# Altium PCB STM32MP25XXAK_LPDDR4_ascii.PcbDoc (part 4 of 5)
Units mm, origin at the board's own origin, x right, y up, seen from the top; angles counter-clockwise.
Board outline 120 x 79.6 mm, 4 copper layers (Top Layer, Signal Layer 1, Signal Layer 2, Bottom Layer), stack 1.614 mm thick; 190 components, 143 nets, 1208 pads, 757 vias.
Unrouted connection lines stored in the file: 3.
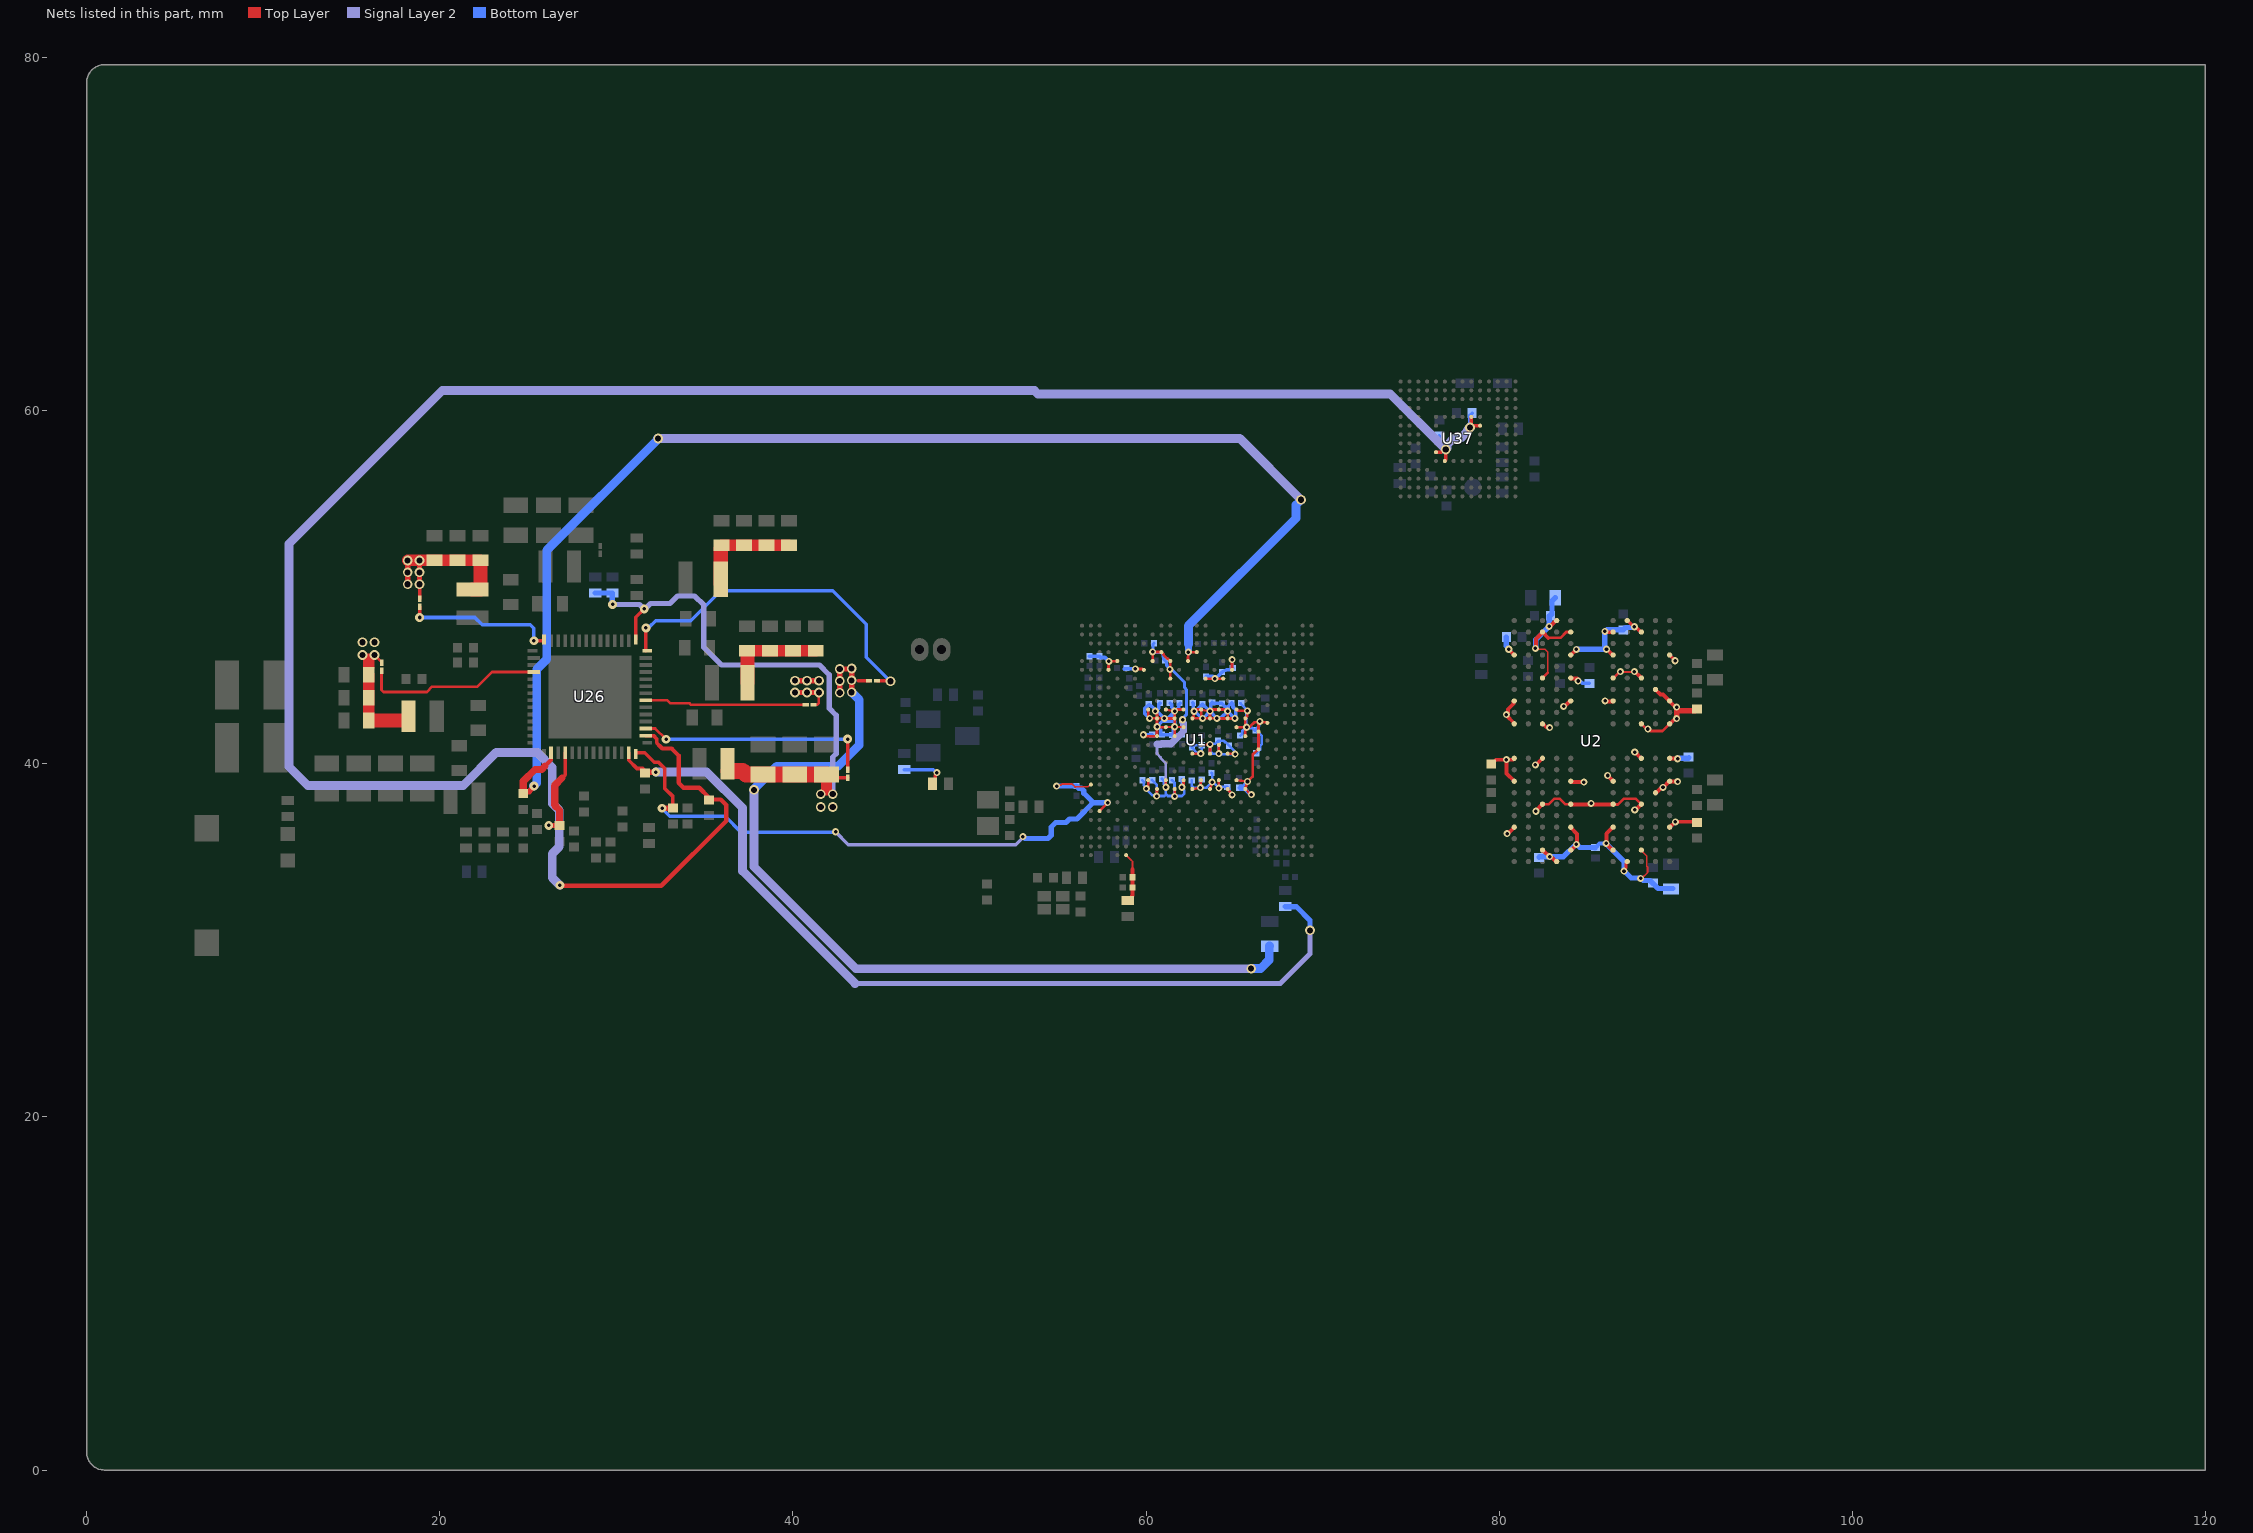
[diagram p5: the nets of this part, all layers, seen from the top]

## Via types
v1: diameter 0.55, hole 0.35, Top Layer to Bottom Layer, 277 vias
v2: diameter 0.4, hole 0.2, Top Layer to Bottom Layer, tented both sides, 229 vias
v3: diameter 0.5, hole 0.2, Top Layer to Bottom Layer, 146 vias
v4: diameter 0.4, hole 0.2, Top Layer to Bottom Layer, 105 vias

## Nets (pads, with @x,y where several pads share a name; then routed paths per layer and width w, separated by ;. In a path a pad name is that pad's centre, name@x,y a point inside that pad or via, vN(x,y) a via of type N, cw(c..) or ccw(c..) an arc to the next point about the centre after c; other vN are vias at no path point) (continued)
VDD2_DDR: C10.2 C11.2 C12.1 C13.1 C14.1 C15.1 C16.1 C17.1 C18.1 C19.1 C20.1 C21.1 C41.2 C75.2 C76.2 C77.1 C82.2 C83.2 C200.2 C202.2 L5.2 LNK8.2 R2.2 U1.1C11 U1.1D12 U1.1E11 U1.1F12 U1.1L11 U1.1M12 U1.M22 U1.N21 U1.R21 U2.A4 U2.A9 U2.AA3 U2.AA5 U2.AA8 U2.AA10 U2.AB4 U2.AB9 U2.B3 U2.B5 U2.B8 U2.B10 U2.D1 U2.D5 U2.D8 U2.D12 U2.F3 U2.F5 U2.F8 U2.F10 U2.G2 U2.H1 U2.H5 U2.H8 U2.H12 U2.K1 U2.K3 U2.K10 U2.K12 U2.N1 U2.N3 U2.N10 U2.N12 U2.R1 U2.R5 U2.R8 U2.R12 U2.T2 U2.U3 U2.U5 U2.U8 U2.U10 U2.W1 U2.W5 U2.W8 U2.W12 | length 84
  Top Layer w0.09: v4@82.121,46.482 82.614,46.482 82.754,46.341 82.754,45.159 ; U2.U5@86.46,44.865 U2.U5@86.48,44.865 ; v4@86.844,45.229 v4(86.865,45.229) 86.89,45.204 87.64,45.204 v4(87.665,45.229) ; U2.AB4@87.26,48.115 U2.AB4@87.285,48.115 ; v4@87.635,47.765 v4(87.659,47.765) ; v4(88.016,33.516) 88.083,33.516 88.405,33.838 88.405,34.168 88.369,34.204 88.369,34.784 U2.B3@88.059,35.094 ; U2.K1@89.659,40.369 U2.K1@89.684,40.369
  Top Layer w0.1: U2.W8@84.06,46.165 U2.W8@84.06,46.167 ; v4@84.38,46.487 v4(84.38,46.49) ; U2.W1@89.66,46.158 U2.W1@89.66,46.165 ; v4(89.972,45.84) v4@89.972,45.846
  Top Layer w0.15: v1(16.298,46.165) 16.7,45.763 LNK8.2@16.7,45.723 ; U1.1L11@65.125,39.075 v2(65.75,39) U1.1M12@65.625,38.575 65.625,38.565 65.9,38.29 65.94,38.29 v2(65.97,38.26) ; U1.1E11@65.125,42.075 65.625,42.075 cw(c65.663,41.93) v2(65.7,42.075) ; U1.1C11@65.125,43.075 65.147,43.075 65.222,43 65.735,43 65.731,42.996 65.731,42.703 65.625,42.597 U1.1D12@65.625,42.575 65.625,42.15 v2(65.7,42.075) ; U1.1F12@65.625,41.575 65.625,42 v2(65.7,42.075) ; v2@65.736,42.111 65.89,42.111 66.137,42.357 v2@66.407,42.357 ; U2.F10@82.459,37.694 82.469,37.704 82.803,37.704 83.129,38.03 83.389,38.03 ; U2.U10@82.46,44.865 82.754,45.159 ; 82.785,47.138 83.478,47.138 83.805,47.465 U2.AA8@84.06,47.465 ; 83.39,38.029 83.43,38.029 83.741,37.719 U2.F8@84.059,37.719 ; U2.F5@86.459,37.694 86.734,37.694 87.072,38.032 87.721,38.032 U2.F3@88.034,37.719 ; U2.U5@86.48,44.865 v4@86.844,45.229
  Top Layer w0.16: v2(65.75,39) 66.042,39.292 66.042,40.512 U1.R21@66.32,40.79 ; U1.R21@66.321,40.79 U1.R21@66.363,40.832 ; U1.R21@66.375,40.825 66.363,40.837 66.363,41.813 U1.N21@66.375,41.825 66.375,42.325 v2(66.45,42.4) 66.493,42.357 66.843,42.357 U1.M22@66.875,42.325 ; v4(87.076,33.92) 87.076,33.985 87.193,34.102 87.193,34.105 87.196,34.108 87.196,34.363 87.26,34.427 U2.A4@87.26,34.465 ; U2.N3@88.06,42.265 88.35,41.975 v4(88.425,41.975) 88.546,41.854 89.249,41.854 U2.N1@89.66,42.265
  Top Layer w0.2: v4@80.546,46.484 v4(80.546,46.49) ; U2.W12@80.86,46.165 U2.W12@80.86,46.171 ; v4(82.835,47.79) 82.873,47.828 v4@82.946,47.828 ; U2.AB9@83.233,48.115 U2.AB9@83.26,48.115 ; v4(85.99,47.505) 86.03,47.465 U2.AA5@86.46,47.465 ; U2.AB4@87.285,48.115 v4@87.635,47.765 ; v4(87.659,47.765) 87.697,47.727 87.771,47.727 88.033,47.465 U2.AA3@88.06,47.465 ; U2.W1@89.66,46.158 v4@89.972,45.846
  Top Layer w0.22: C13.1@79.559,39.979 79.814,40.235 v4(80.415,40.235) ; v4@80.488,36.045 80.51,36.045 U2.D12@80.859,36.394 ; v4@80.546,46.484 U2.W12@80.86,46.171 ; U2.H12@80.859,39.021 80.421,39.459 80.421,40.229 v4(80.415,40.235) ; U2.K12@80.859,40.294 80.856,40.297 U2.K12@80.842,40.297 ; U2.K12@80.86,40.315 U2.K12@80.842,40.297 ; U2.N12@80.86,42.265 80.86,42.301 80.414,42.747 v4(80.414,42.784) 80.414,42.832 80.504,42.922 80.504,42.924 80.51,42.93 80.51,43.093 80.82,43.403 80.82,43.503 80.86,43.543 U2.R12@80.86,43.565 ; v4@82.059,39.919 82.072,39.919 82.447,40.294 U2.K10@82.459,40.294 ; v4@82.086,37.344 82.436,37.694 U2.F10@82.459,37.694 ; v4@82.089,46.574 82.089,47.074 82.459,47.444 82.479,47.444 82.785,47.138 ; U2.B10@82.459,35.094 82.462,35.097 82.493,35.097 82.845,34.744 v4(82.86,34.744) ; U2.N10@82.459,42.244 82.491,42.244 82.497,42.25 82.672,42.074 82.826,42.074 v4@82.86,42.04 ; v4@82.859,34.719 82.893,34.685 82.997,34.685 83.237,34.444 U2.A9@83.259,34.444 ; v4@82.946,47.828 U2.AB9@83.233,48.115 ; v4(83.66,43.253) 83.704,43.253 84.016,43.565 U2.R8@84.06,43.565 ; U2.B8@84.059,35.094 v4@84.384,35.419 ; U2.D8@84.059,36.394 84.419,36.034 v4@84.419,35.503 ; U2.F8@84.059,37.719 84.072,37.707 85.122,37.707 85.134,37.719 85.147,37.707 86.447,37.707 U2.F5@86.459,37.694 ; U2.H8@84.059,39.015 84.081,39.015 84.131,38.965 v4(84.809,38.965) ; U2.U8@84.059,44.844 84.074,44.829 84.426,44.829 84.46,44.794 v4@84.509,44.794 ; U2.W8@84.06,46.167 v4@84.38,46.487 ; v4(86.01,43.565) 86.042,43.532 U2.R5@86.422,43.532 ; v4(86.085,46.49) 86.11,46.49 86.435,46.165 U2.W5@86.46,46.165 ; v4(86.145,39.34) U2.H5@86.46,39.025 ; U2.B5@86.459,35.094 86.059,35.494 86.089,35.524 86.089,36.044 U2.D5@86.46,36.415 ; v4@87.679,45.243 88.032,44.891 88.032,44.883 U2.U3@88.059,44.856 ; v4(87.685,37.39) 87.733,37.39 87.817,37.474 88.037,37.694 U2.F3@88.059,37.694 ; v4(87.685,40.665) 87.697,40.665 88.046,40.316 U2.K3@88.059,40.316 ; U2.T2@88.832,44.199 88.854,44.199 89.134,43.919 89.284,43.919 89.95,43.253 90.025,43.253 v4@90.059,43.219 ; U2.G2@88.859,38.344 88.881,38.344 v4@89.171,38.635 ; v4(89.285,38.665) 89.298,38.665 89.628,38.995 89.658,38.995 89.659,38.994 v4@90.109,38.994 ; U2.D1@89.659,36.394 89.984,36.719 C15.1@91.159,36.719 ; U2.K1@89.659,40.307 89.659,40.294 v4@90.109,40.294 ; U2.N1@89.659,42.244 89.95,42.535 90.025,42.535 v4@90.059,42.569 ; v4(80.415,40.235) 80.78,40.235 U2.K12@80.842,40.297
  Top Layer w0.3: v4@90.059,42.569 v4@90.059,43.219 ; 90.259,43.014 91.079,43.014 C14.1@91.184,43.119
  Top Layer w0.64: C202.2@15.975,42.45 C41.2@15.975,43.75 C200.2@15.975,45.05 ; 15.975,45.495 15.975,45.925
  Top Layer w0.8: C202.2@16.2,42.45 L5.2@17.975,42.45
  Bottom Layer w0.15: C83.2@65.35,43.425 v2@65.627,43.148 ; C82.2@65.352,41.603 65.452,41.703 65.452,41.862 v2@65.625,42.035 ; v2@65.625,42.075 65.625,42.143 65.675,42.193 v2@65.675,42.99 ; v2@65.673,42.027 66.023,42.027 66.183,41.867 C75.2@66.218,41.867 ; C75.2@66.205,41.9 66.305,41.8 66.331,41.8 66.431,41.7 66.452,41.7 66.555,41.597 66.555,41.109 66.474,41.028 66.474,40.824 66.47,40.82
  Bottom Layer w0.16: C75.2@66.175,41.9 66.27,41.995 66.27,42.018 66.404,42.152 66.404,42.354 v2(66.45,42.4) ; C77.1@66.25,40.6 66.345,40.695 66.348,40.695 66.47,40.817 66.47,40.82
  Bottom Layer w0.2: v2(65.75,39) 65.476,38.726 65.466,38.726 65.463,38.723 65.349,38.723 C76.2@65.274,38.648 65.349,38.573 65.607,38.573 65.92,38.26 v2(65.97,38.26)
  Bottom Layer w0.22: v4@84.509,44.79 84.73,44.569 85.105,44.569 C21.1@85.109,44.565 ; R2.2@85.409,35.215 85.459,35.215 85.549,35.305 85.549,35.355 85.684,35.49 v4(86.06,35.49)
  Bottom Layer w0.3: C12.1@80.411,47.18 80.41,46.671 80.547,46.534 v4@80.547,46.485 ; v4@82.061,46.535 82.08,46.554 82.08,47.029 v4@82.836,47.785 ; C19.1@82.26,34.705 82.3,34.744 83.653,34.744 84.324,35.415 84.378,35.415 84.402,35.44 84.577,35.265 R2.2@85.461,35.265 ; v4(82.835,47.79) 82.834,48.365 C16.1@82.91,48.441 ; C16.1@82.911,48.39 82.996,48.475 82.996,49.225 C10.2@83.186,49.415 ; v4@84.381,46.485 86.086,46.485 86.086,46.534 85.991,46.629 85.991,47.499 86.04,47.499 86.13,47.59 C17.1@87.036,47.59 87.17,47.725 87.626,47.725 v4@87.66,47.76 ; v4(86.06,35.49) 87.077,34.473 87.077,33.915 87.104,33.915 87.489,33.531 87.998,33.531 88.017,33.511 88.088,33.455 88.162,33.397 88.553,33.397 88.58,33.345 C18.1@88.705,33.244 ; C18.1@88.604,33.345 C18.1@88.705,33.244 ; C18.1@88.71,33.24 C18.1@88.705,33.244 ; C11.2@89.834,32.94 89.009,32.94 C18.1@88.705,33.244 ; v4@90.109,40.29 90.143,40.324 90.718,40.324 C20.1@90.759,40.365
  other v1: 15.623,46.165 15.623,46.89 16.298,46.89
  other v2: 65.743,43
  other v4: 84.375,35.44 80.46,36.045 89.985,36.715 82.085,37.315 85.21,37.765 90.11,38.99 82.06,39.94 90.11,40.29 82.86,42.05 90.06,42.565 90.06,43.215 84.479,44.694 82.06,46.54
VDD3V3_USB: C61.2 R286.1 U26.13 | length 50.7
  Top Layer w0.21: U26.13@30.7,40.63 30.7,40.2 31.163,39.737 31.418,39.737 31.42,39.735 31.49,39.735 31.625,39.6 C61.2@31.625,39.53
  Top Layer w0.3: C61.2@31.625,39.53 v3(32.235,39.53)
  Signal Layer 2 w0.3: 43.518,27.562 67.603,27.562 69.284,29.244 v1(69.284,30.569)
  Signal Layer 2 w0.5: v3(32.235,39.53) 35.12,39.53 37.15,37.5 37.15,33.93 43.518,27.562
  Bottom Layer w0.3: R286.1@67.89,31.915 67.898,31.908 68.514,31.908 69.284,31.138 v1(69.284,30.569)
VDD_DDR_FB: LNK8.1 U26.46 | length 10.2
  Top Layer w0.15: LNK8.1@16.7,45.273 16.7,44.19 16.817,44.073 19.267,44.073 19.567,44.373 20.237,44.373 20.239,44.375 22.127,44.375 22.952,45.2 U26.46@25.33,45.2
VDD_EMMC: C9.2 C117.2 C190.1 U26.16 U37.E6 U37.F5 U37.J10 U37.K9 | length 132.2
  Top Layer w0.2: U37.E6@76.425,57.655 76.73,57.655 76.88,57.805 v1(76.975,57.805) 76.975,57.213 76.925,57.163 U37.F5@76.925,57.155 ; v1(78.35,59.055) v1@78.425,59.13 ; U37.J10@78.425,59.655 78.425,59.225 78.417,59.217 78.417,59.138 v1@78.425,59.13 ; U37.K9@78.925,59.155 78.545,59.155 78.512,59.122 78.433,59.122 v1@78.425,59.13
  Top Layer w0.21: U26.16@31.67,41.6 32.1,41.6 32.288,41.412 32.288,41.187 32.434,41.041
  Top Layer w0.25: v3@26.752,33.092 32.549,33.092 36.225,36.768 36.225,37.668 35.912,37.981 C190.1@35.266,37.981 ; 32.432,41.038 32.598,40.872 33.128,40.872 33.525,40.475 33.525,38.925 33.8,38.65 34.695,38.65 35.25,38.095 C190.1@35.25,38.025
  Signal Layer 2 w0.5: v3(26.8,33.125) 26.372,33.553 26.372,34.908 26.765,35.301 26.765,37.369 26.372,37.762 26.372,39.786 25.509,40.649 23.203,40.649 21.327,38.773 12.524,38.773 11.458,39.839 11.458,52.457 20.147,61.146 53.676,61.146 53.869,60.953 73.827,60.953 76.886,57.894 v1(76.975,57.805) 76.975,57.819 77.05,57.894 77.05,58.059 77.431,58.44 77.819,58.44 78.2,58.821 78.2,58.891 78.34,59.032 v1@78.34,59.045
  Bottom Layer w0.2: C9.2@76.615,58.58 76.615,58.074 76.884,57.805 v1(76.975,57.805) ; v1(78.35,59.055) 78.35,59.739 C117.2@78.475,59.864
VDD_SDCARD: C215.1 U26.4 | length 5.1
  Top Layer w0.21: 26.925,39.2 27.1,39.375 U26.4@27.1,40.63
  Top Layer w0.3: v3(26.165,36.51) C215.1@26.775,36.51
  Top Layer w0.4: C215.1@26.775,36.51 26.775,37.393 26.51,37.658 26.51,38.785 26.925,39.2
VDDA1V8_AON: C189.2 C234.2 U1.AB3 U1.W2 U26.14 | length 37.9
  Top Layer w0.09: 56.026,38.692 56.705,38.692 56.837,38.825 U1.W2@56.875,38.825 ; v2@57.825,37.775 v2(57.825,37.8)
  Top Layer w0.1: v2(54.932,38.744) 54.99,38.801 55.205,38.801 55.267,38.863 55.805,38.863 55.975,38.692 56.026,38.692
  Top Layer w0.15: U1.AB3@57.375,37.325 v2@57.825,37.775
  Top Layer w0.21: U26.14@31.1,40.63 31.61,40.63 32.148,40.092 32.387,40.092 32.745,39.734 32.745,38.602 33.2,38.147 C189.2@33.2,37.49
  Top Layer w0.3: v3(32.59,37.49) C189.2@33.2,37.49
  Signal Layer 2 w0.2: v2(42.415,36.154) 43.144,35.425 52.627,35.425 53.025,35.823 v2(53.025,35.875)
  Bottom Layer w0.2: v3@32.57,37.493 33.032,37.031 36.158,37.031 37.056,36.133 42.394,36.133 v2(42.415,36.154)
  Bottom Layer w0.3: v2(53.025,35.875) 53.052,35.875 53.152,35.775 53.829,35.775 53.836,35.769 54.451,35.769 54.627,35.944 54.627,36.412 54.891,36.675 55.461,36.675 55.662,36.877 56.088,36.877 57.012,37.8 ; v2(54.932,38.744) 54.936,38.748 C234.2@56.064,38.748 56.199,38.613 56.338,38.613 56.479,38.472 56.479,38.333 57.012,37.8 ; v2(57.825,37.8) 57.012,37.8
VDDCORE: C22.2 C23.2 C24.2 C44.1 C45.2 C46.2 C47.1 C48.2 C49.2 C50.2 C51.2 C183.2 C192.2 C197.2 C201.2 L2.2 LNK2.2 R11.1 U1.1C1 U1.1C3 U1.1C5 U1.1D2 U1.1D4 U1.1E3 U1.1E5 U1.1F2 U1.1F4 U1.E5 U1.F4 U1.F8 | length 78.4
  Top Layer w0.15: U1.F4@57.875,45.325 v2(57.9,45.8) U1.E5@58.375,45.825 ; v2(59.4,45.375) 59.803,45.375 59.853,45.325 U1.F8@59.875,45.325 ; v2(59.85,41.65) 59.904,41.65 59.981,41.573 U1.1F2@60.624,41.573 ; U1.1C1@60.125,43.075 60.125,42.724 60.206,42.643 v2@60.206,42.575 ; v2(60.21,42.575) U1.1D2@60.625,42.575 ; v2@60.545,42.99 60.545,42.922 60.625,42.842 U1.1D2@60.625,42.575 ; U1.1F2@60.625,41.65 v2(60.625,42.1) ; U1.1C3@61.125,43.075 v2(61.625,42.983) ; U1.1F4@61.625,41.575 v2(61.625,42.1) ; U1.1E5@62.125,42.075 v2(61.625,42.1) ; U1.1C5@62.125,43.075 61.771,43.075 61.679,42.983 v2(61.625,42.983) ; v2(60.625,42.1) U1.1D2@60.625,42.575 ; v2(60.625,42.1) 60.65,42.075 U1.1E3@61.125,42.075 v2(61.625,42.1) ; U1.1D2@60.625,42.575 61.017,42.572 61.622,42.572 U1.1D4@61.625,42.575 ; v2(61.625,42.1) U1.1D4@61.625,42.575 ; U1.1D4@61.625,42.575 v2@61.625,42.983
  Top Layer w0.2: C22.2@39.775,52.375 C22.2@39.823,52.423 ; 43.7,44.7 LNK2.2@44.316,44.7
  Top Layer w0.3: v1(42.656,44.024) v1(42.656,44.699) v1(42.656,45.374) 43.331,45.374 v1@43.331,44.024
  Top Layer w0.64: C183.2@35.95,52.375 C24.2@37.225,52.375 C23.2@38.5,52.375 C22.2@39.775,52.375
  Top Layer w0.8: L2.2@35.915,50.2 L2.2@35.915,50.45 C183.2@35.915,52.173
  Signal Layer 2 w0.5: v1(37.8,38.525) 37.798,38.523 37.798,34.168 43.576,28.39 v1@65.911,28.39 ; v1@65.911,28.391 65.947,28.391 v1(65.956,28.4)
  Bottom Layer w0.2: C192.2@56.8,46.1 C201.2@57.375,46.1 57.45,46.025 57.675,46.025 v2(57.9,45.8) ; C197.2@58.755,45.355 58.775,45.375 v2(59.4,45.375) ; v2(59.85,41.65) 60.346,41.65 C44.1@60.351,41.655 ; v2@60.206,42.575 59.942,42.839 59.942,43.153 60.059,43.27 60.098,43.27 60.173,43.345 60.198,43.32 60.235,43.32 60.285,43.27 60.328,43.27 60.507,43.091 60.507,43.028 60.545,42.99 v2@60.578,42.99 ; C51.2@60.814,43.438 60.788,43.438 60.725,43.375 60.725,43.137 v2@60.578,42.99 ; C46.2@60.84,41.657 C46.2@60.913,41.657 ; C46.2@60.915,41.655 C46.2@60.913,41.657 ; v2@61.135,42.572 61.017,42.572 61.017,42.591 60.719,42.89 60.699,42.89 60.599,42.99 v2@60.578,42.99 ; C49.2@61.377,43.437 61.452,43.362 61.452,43.201 61.625,43.028 v2(61.625,42.983) v2@61.616,42.961 ; C47.1@61.476,41.631 C47.1@61.502,41.657 ; C50.2@61.941,43.438 61.866,43.363 61.866,43.211 v2@61.616,42.961 ; C48.2@62.038,41.657 C47.1@61.502,41.657 ; C46.2@60.913,41.657 C47.1@61.502,41.657 ; C46.2@60.913,41.657 60.84,41.73 60.84,41.94 60.719,42.062 60.663,42.062 v2(60.625,42.1) 60.625,42.107 60.923,42.405 v2@61.06,42.405 ; v2@61.06,42.405 v2@61.227,42.572 ; v2@61.06,42.405 61.623,42.405 ; v2@61.227,42.572 v2@61.616,42.961 ; v2@61.227,42.572 61.455,42.572 ; 61.455,42.572 v2@61.616,42.961 ; 61.455,42.572 61.623,42.405 ; C47.1@61.502,41.657 61.551,41.706 61.551,41.972 61.625,42.046 v2(61.625,42.1) 61.623,42.102 61.623,42.405
  Bottom Layer w0.5: v1(37.8,38.525) 37.81,38.535 37.81,38.592 39.084,39.866 42.555,39.866 43.757,41.068 43.757,43.623 v1(43.326,44.054) ; v1(65.956,28.4) 66.485,28.4 66.983,28.898 66.983,29.658 R11.1@67,29.675
  other v1: 43.326,44.729 43.326,45.404
  other v2: 61.04,42.575 60.531,42.99
VDDCORE_FB: LNK2.1 U26.28 | length 20.6
  Top Layer w0.2: U26.28@31.67,46.4 v3(31.67,47.7) ; LNK2.1@44.766,44.7 v1@45.376,44.7
  Bottom Layer w0.2: v3@31.645,47.7 31.702,47.757 31.876,47.757 32.229,48.111 34.209,48.111 35.902,49.804 42.248,49.804 44.15,47.902 44.15,46.041 v1@45.508,44.683 ; v3@31.65,47.703 31.707,47.761 31.881,47.761 32.234,48.114
  other v1: 45.533,44.683
VDDCPU: C26.2 C27.2 C28.2 C62.1 C63.2 C64.2 C65.1 C66.2 C67.2 C68.2 C69.2 L3.2 LNK4.1 U1.1C7 U1.1C9 U1.1D6 U1.1D8 U1.1D10 U1.F18 U1.G15 U1.G17 | length 28.3
  Top Layer w0.15: v2@62.725,42.907 v2@62.725,42.975 ; v2@63.2,42.575 U1.1D6@62.625,42.575 62.625,42.597 62.696,42.668 62.696,42.956 v2(62.72,42.98) 62.788,42.98 62.883,43.075 U1.1C7@63.125,43.075 ; U1.G15@63.375,44.825 v2(63.9,44.825) U1.G17@64.375,44.825 ; U1.F18@64.875,45.325 v2(64.875,45.91) ; v2@65.017,42.572 64.628,42.572 U1.1D10@64.625,42.575 ; U1.1C7@63.125,43.075 63.125,42.728 63.21,42.643 v2(63.21,42.575) U1.1D8@63.625,42.575 ; U1.1C7@63.125,43.075 v2(63.625,42.983) ; U1.1D8@63.625,42.575 v2(63.625,42.983) ; U1.1D8@63.625,42.575 v2(64.017,42.572) 64.622,42.572 U1.1D10@64.625,42.575 ; v2(63.625,42.983) 63.693,42.983 63.784,43.075 U1.1C9@64.125,43.075 64.466,43.075 64.557,42.983 v2(64.625,42.983) U1.1D10@64.625,42.575
  Top Layer w0.2: LNK4.1@18.85,49.35 v1(18.85,50.173)
  Top Layer w0.3: v1(18.175,50.173) v1(18.175,50.848) v1(18.175,51.523) v1(18.85,51.523) v1(18.85,50.848) v1(18.85,50.173)
  Top Layer w0.64: v1(18.175,51.523) v1(18.175,51.523) C27.2@19.7,51.525 C28.2@21,51.525 C26.2@22.3,51.525
  Top Layer w0.8: L3.2@21.85,49.875 22.3,49.875 22.3,51.173
  Bottom Layer w0.15: v2(64.875,45.91) 64.895,45.89 C66.2@64.895,45.441
  Bottom Layer w0.2: C63.2@62.65,43.455 62.685,43.42 v2@62.685,43.015 ; C67.2@63.4,44.95 63.775,44.95 v2(63.9,44.825) 63.933,44.825 64.23,45.122 64.23,45.127 64.3,45.197 C69.2@64.305,45.197 ; v2(64.017,42.572) 64.055,42.61 64.252,42.61 v2(64.625,42.983) ; v2@64.017,42.583 v2@63.625,42.975 ; C69.2@64.305,45.202 64.579,45.324 64.778,45.324 64.886,45.432 64.91,45.423 C66.2@64.915,45.421 ; v2@63.625,42.975 v2(63.625,42.983) ; v2@63.625,42.975 63.625,42.963 63.237,42.575 63.169,42.575 62.764,42.98 v2(62.72,42.98) 62.758,43.018 62.843,43.018 C62.1@63.2,43.375 63.275,43.3 63.308,43.3 v2(63.625,42.983) ; v2(63.625,42.983) 63.625,43.038 63.675,43.088 63.675,43.4 C65.1@63.75,43.475 63.784,43.441 64.284,43.441 C68.2@64.3,43.425 64.587,43.138 64.587,43.022 v2(64.625,42.983) ; v2(64.625,42.983) 64.658,43.016 64.658,43.258 C64.2@64.85,43.45 64.925,43.375 64.925,43.22 65.086,43.059 65.086,42.672 65.04,42.626 v2(65.04,42.572) 65.036,42.572 v2(64.625,42.983)
VDDCPU_FB: LNK4.2 U26.42 | length 8.6
  Top Layer w0.2: v3(18.85,48.29) LNK4.2@18.85,48.9 ; v3(25.325,46.975) U26.42@25.895,46.975
  Bottom Layer w0.2: v3(18.85,48.29) 21.979,48.29 22.394,47.875 25.123,47.875 25.325,47.673 v3(25.325,46.975)
VDDGPU: C34.2 C35.2 C36.2 C37.2 C52.2 C53.2 C54.2 C55.2 C57.2 C58.2 C59.2 C60.2 L4.2 LNK7.2 U1.1G7 U1.1G9 U1.1H6 U1.1H8 U1.1H10 U1.1L7 U1.1L9 U1.1M6 U1.1M8 U1.1M10 | length 24.7
  Top Layer w0.1: U1.1H6@62.625,40.575 U1.1H6@62.625,40.61
  Top Layer w0.125: v2(64.125,40.575) U1.1G9@64.125,41.075
  Top Layer w0.15: LNK7.2@41.175,43.35 41.182,43.358 41.385,43.358 41.473,43.445 v1(41.473,44.038) ; U1.1M6@62.625,38.575 v2(63.075,38.65) U1.1L7@63.125,39.075 ; U1.1H6@62.625,40.575 v2(63.1,40.575) ; U1.1G7@63.125,41.075 v2(63.625,41.1) U1.1H8@63.625,40.575 ; U1.1M8@63.625,38.575 v2(63.747,38.971) ; v2(64.125,38.629) U1.1L9@64.125,39.075 ; U1.1M10@64.625,38.575 v2(64.876,38.245)
  Top Layer w0.16: U1.1H10@64.625,40.575 v2(65.05,40.55)
  Top Layer w0.2: C35.2@41.55,46.393 C35.2@41.598,46.345
  Top Layer w0.3: v1(40.123,44.038) v1(40.798,44.038) v1(41.473,44.038) ; v1(40.123,44.713) v1(40.798,44.713) v1(41.473,44.713)
  Top Layer w0.64: C37.2@37.4,46.4 C36.2@38.7,46.4 C34.2@40,46.4 C35.2@41.3,46.4
  Top Layer w0.8: L4.2@37.425,44.6 37.425,46.073
  Bottom Layer w0.15: C57.2@62.592,39.053 62.592,38.738 62.68,38.65 v2(63.075,38.65) ; C60.2@63.154,39.122 63.092,39.06 63.092,38.667 v2(63.075,38.65) ; C59.2@63.714,39.486 63.747,39.453 v2(63.747,38.971) ; v2(64.876,38.245) 64.876,38.289 64.707,38.458 64.707,38.597 C58.2@64.607,38.697 64.193,38.697 v2(64.125,38.629) 63.783,38.971 v2(63.747,38.971) ; v2(63.075,38.65) 63.426,38.65 v2(63.747,38.971) ; C52.2@63.162,41.057 62.788,41.057 62.756,41.025 62.7,41.025 C55.2@62.6,40.925 62.902,40.623 63.052,40.623 v2(63.1,40.575) 63.162,40.637 C52.2@63.162,41.057 ; C52.2@63.162,41.057 63.184,41.079 63.603,41.079 v2(63.625,41.1) ; v2(63.625,41.1) 63.656,41.131 63.908,41.131 C53.2@64.083,41.306 ; v2(63.625,41.1) 63.625,40.719 63.769,40.575 v2(64.125,40.575) ; C53.2@64.083,41.306 64.396,41.306 64.463,41.239 64.496,41.239 C54.2@64.706,41.029 65.002,40.733 65.002,40.598 v2(65.05,40.55) 64.15,40.55 v2(64.125,40.575) ; C53.2@64.083,41.306 64.083,40.962 64.125,40.919 v2(64.125,40.575)
VDDGPU_FB: LNK7.1 U26.21 | length 9.3
  Top Layer w0.15: U26.21@31.55,43.6 32.883,43.6 33.06,43.423 34.14,43.423 34.213,43.35 LNK7.1@40.725,43.35
VDDIO: C70.1 C71.2 C72.2 C73.1 C74.2 C185.2 C186.2 C187.2 C196.2 C205.2 L6.2 LNK11.2 R27.2 R67.2 R260.2 R261.2 U1.1L1 U1.1L3 U1.1L5 U1.1M2 U1.1M4 U1.D10 U1.E9 U1.E11 U1.G11 U26.29 | length 59.1
  Top Layer w0.15: v2(60.025,38.6) 60.025,38.618 60.125,38.718 U1.1L1@60.125,39.075 ; U1.E9@60.375,45.825 U1.E9@60.397,45.825 ; U1.E9@60.375,45.825 v2(60.375,46.344) ; v2@60.448,46.335 U1.D10@60.865,46.335 ; v2(60.6,38.175) U1.1M2@60.625,38.575 ; U1.D10@60.875,46.325 60.875,46.322 61,46.197 61,46.17 61.22,45.95 61.247,45.95 61.372,45.825 U1.E11@61.375,45.825 61.375,45.448 61.362,45.435 61.375,45.423 U1.G11@61.375,44.825 ; v2(61.125,38.675) U1.1L3@61.125,39.075 ; U1.1M4@61.625,38.575 61.625,38.212 v2@61.663,38.175 ; v2@62.05,38.675 62.05,38.743 62.125,38.818 U1.1L5@62.125,39.075
  Top Layer w0.2: U26.29@31.1,47.045 31.1,48.298 v3(31.575,48.773) ; C186.2@41.9,39.4 42.085,39.215 LNK11.2@43.1,39.215 ; R27.2@47.905,38.872 48.06,39.027 48.06,39.347 48.158,39.446 v2(48.158,39.5)
  Top Layer w0.64: 41.9,38.525 C186.2@41.9,38.955
  Top Layer w0.9: L6.2@36.35,39.6 37.15,39.6 37.35,39.4 C187.2@38.3,39.4 C185.2@40.1,39.4 C186.2@41.9,39.4
  Signal Layer 2 w0.15: 60.633,41.112 60.619,41.098 60.619,40.581 60.827,40.373 60.827,40.328 61.125,40.03 v2(61.125,38.675)
  Signal Layer 2 w0.3: v3(29.784,49.027) 31.299,49.027 31.55,48.776 v3@31.575,48.776 ; v3(31.575,48.773) 31.629,48.773 31.94,49.084 33.043,49.084 33.473,49.513 34.431,49.513 34.955,48.989 34.955,46.601 35.956,45.6 41.499,45.6 42.051,45.048 42.051,43.156 42.451,42.756 42.451,40.573 42.252,40.375 v1(42.252,38.285)
  Signal Layer 2 w0.4: 60.633,41.112 60.859,41.112 60.885,41.138 61.426,41.138 62.125,41.837 62.125,42.307 62.072,42.36 v2(62.072,42.497)
  Bottom Layer w0.15: C70.1@59.781,39.075 59.881,38.975 59.881,38.787 60.025,38.643 60.025,38.55 60.352,38.223 60.552,38.223 v2(60.6,38.175) ; C71.2@60.34,39.085 60.6,38.825 v2(60.6,38.175) ; C72.2@60.905,39.148 61.005,39.048 61.005,38.863 61.125,38.743 v2(61.125,38.675) 61.125,38.285 ; C73.1@61.467,39.074 61.61,38.931 v2@61.61,38.175 ; v2(61.625,38.16) v2@61.61,38.175 ; C74.2@62.03,39.133 62.04,39.123 62.04,38.685 62.05,38.675 62.05,38.607 62.175,38.482 62.175,38.323 62.027,38.175 v2@61.61,38.175 ; v2(60.6,38.175) 61.037,38.175 61.125,38.263 61.125,38.285 ; 61.125,38.285 61.235,38.175 v2@61.61,38.175
  Bottom Layer w0.175: C205.2@60.452,46.829 60.389,46.765 v2@60.389,46.357 ; v2@60.485,46.38 60.411,46.38 v2@60.389,46.357 ; v2@61.35,45.366 61.35,45.39 61.175,45.565 61.175,45.66 61.163,45.672 61.163,45.762 61,45.925 61,46.01 60.968,46.042 60.968,46.188 60.85,46.305 60.413,46.305 v2(60.375,46.344) v2@60.389,46.357 ; v2@61.362,45.435 62.186,44.612 62.186,44.315 62.253,44.249 62.253,44.231 62.283,44.2 62.283,42.776 62.072,42.564 v2(62.072,42.497)
  Bottom Layer w0.2: R67.2@46.3,39.675 47.941,39.675 48.116,39.5 v2(48.158,39.5)
  Bottom Layer w0.3: R260.2@28.81,49.683 29.785,49.683 29.774,49.673 29.774,49.041 v3@29.764,49.031
  other v1: 41.577,37.56 42.252,37.56 41.577,38.285
  other v2: 62.03,38.675 61.35,45.35
VDDIO_FB: LNK11.1 U26.17 | length 13.4
  Top Layer w0.15: U26.17@31.67,42 32.2,42 32.803,41.397 v3(32.815,41.397)
  Top Layer w0.2: LNK11.1@43.1,39.665 v3(43.1,41.4)
  Bottom Layer w0.15: v3@43.097,41.397 v3(43.1,41.4)
  Bottom Layer w0.2: v3(32.815,41.397) v3@43.097,41.397
VDDIO_SDCARD: C195.2 C217.1 U1.D14 U1.E13 U26.2 | length 76.7
  Top Layer w0.15: U1.E13@62.375,45.825 v2(62.4,46.325) U1.D14@62.875,46.325
  Top Layer w0.21: 25.959,39.873 26.3,40.214 U26.2@26.3,40.63
  Top Layer w0.3: C217.1@24.725,38.38 24.77,38.425 25.059,38.425 25.335,38.701 v3(25.335,38.737)
  Top Layer w0.4: C217.1@24.725,38.32 24.725,38.38 24.725,39.015 25.399,39.69 25.775,39.69 25.959,39.873
  Signal Layer 2 w0.5: v1(32.365,58.43) 32.368,58.432 51.443,58.432 ; 51.445,58.435 51.443,58.432 ; v1(68.777,54.958) 65.303,58.432 51.443,58.432
  Bottom Layer w0.4: v2(62.4,46.325) C195.2@62.4,46.787
  Bottom Layer w0.5: v3@25.315,38.74 25.489,38.914 25.489,45.364 26.061,45.936 26.061,52.095 32.335,58.37 32.335,58.424 v1@32.345,58.433 ; C195.2@62.4,46.787 62.4,47.824 68.495,53.919 68.495,54.661 68.777,54.944 v1(68.777,54.958)
VREF+: C248.2 C250.2 R269.2 U1.AG6 | length 2.9
  Top Layer w0.09: U1.AG6@58.875,34.825 59.13,34.57
  Top Layer w0.1: 59.13,34.57 59.233,34.467 59.233,34.02
  Top Layer w0.25: R269.2@58.956,32.258 59.051,32.258 59.181,32.388 59.181,32.483 59.233,32.535 C248.2@59.233,33.002 C250.2@59.233,33.572 59.233,34.02
pads on no net: U1.A3 U1.A6 U1.A7 U1.A10 U1.A11 U1.A14 U1.A15 U1.A18 U1.A19 U1.A26 U1.AA3 U1.AA5 U1.AA7 U1.AA9 U1.AA11 U1.AA13 U1.AA15 U1.AA17 U1.AA19 U1.AA21 U1.AA23 U1.AB1 U1.AB2 U1.AB8 U1.AB10 U1.AB12 U1.AB14 U1.AB16 U1.AB18 U1.AB24 U1.AC2 U1.AC7 U1.AC9 U1.AC13 U1.AC15 U1.AC17 U1.AC19 U1.AC23 U1.AC25 U1.AD4 U1.AD6 U1.AD8 U1.AD10 U1.AD12 U1.AD14 U1.AD16 U1.AD18 U1.AD20 U1.AD24 U1.AD25 U1.AE2 U1.AE3 U1.AE4 U1.AE5 U1.AE6 U1.AE7 U1.AE8 U1.AE9 U1.AE10 U1.AE11 U1.AE12 U1.AE13 U1.AE14 U1.AE15 U1.AE16 U1.AE17 U1.AE18 U1.AE19 U1.AE20 U1.AE24 U1.AE25 U1.AE26 U1.AF1 U1.AF3 U1.AF7 U1.AF9 U1.AF10 U1.AF11 U1.AF13 U1.AF14 U1.AF15 U1.AF17 U1.AF18 U1.AF19 U1.AF21 U1.AF22 U1.AF23 U1.AF25 U1.AF26 U1.AF27 U1.AG5 U1.AG9 U1.AG10 U1.AG13 U1.AG14 U1.AG17 U1.AG18 U1.AG21 U1.AG22 U1.AG25 U1.AG26 U1.B1 U1.B2 U1.B3 U1.B5 U1.B6 U1.B7 U1.B9 U1.B10 U1.B11 U1.B13 U1.B14 U1.B15 U1.B17 U1.B18 U1.B19 U1.B21 U1.B26 U1.B27 U1.C2 U1.C3 U1.C4 U1.C5 U1.C7 U1.C8 U1.C9 U1.C11 U1.C12 U1.C13 U1.C14 U1.C15 U1.C16 U1.C17 U1.C18 U1.C19 U1.C20 U1.C21 U1.C22 U1.C26 U1.C27 U1.D3 U1.D4 U1.D6 U1.D8 U1.D12 U1.D16 U1.D20 U1.D25 U1.E1 U1.E2 U1.E3 U1.F1 U1.F2 U1.F6 U1.F10 U1.G2 U1.G3 U1.G13 U1.G21 U1.H3 U1.H4 U1.J1 U1.J2 U1.J3 U1.J5 U1.K1 U1.K2 U1.K4 U1.K6 U1.K24 U1.L2 U1.L3 U1.L5 U1.L7 U1.L21 U1.M3 U1.M4 U1.M6 U1.N1 U1.N2 U1.N3 U1.N5 U1.N7 U1.P1 U1.P2 U1.P3 U1.P4 U1.P6 U1.R2 U1.R3 U1.R5 U1.T3 U1.T4 U1.U1 U1.U2 U1.U3 U1.U5 U1.U7 U1.V1 U1.V2 U1.V3 U1.V4 U1.W5 U1.W21 U1.W23 U1.Y3 U1.Y6 U1.Y22 U2.A1 U2.A2 U2.A8 U2.A11 U2.A12 U2.AA1 U2.AA12 U2.AB1 U2.AB2 U2.AB11 U2.AB12 U2.B1 U2.B12 U2.G11 U2.H3 U2.J5 U2.K5 U2.K8 U2.N5 U2.N8 U2.P5 U2.R3 U37.A1 U37.A2 U37.A7 U37.A8 U37.A9 U37.A10 U37.A11 U37.A12 U37.A13 U37.A14 U37.B1 U37.B7 U37.B8 U37.B9 U37.B10 U37.B11 U37.B12 U37.B13 U37.B14 U37.C1 U37.C3 U37.C5 U37.C7 U37.C8 U37.C9 U37.C10 U37.C11 U37.C12 U37.C13 U37.C14 U37.D1 U37.D2 U37.D3 U37.D4 U37.D12 U37.D13 U37.D14 U37.E1 U37.E2 U37.E3 U37.E5 U37.E8 U37.E9 U37.E10 U37.E12 U37.E13 U37.E14 U37.F1 U37.F2 U37.F3 U37.F10 U37.F12 U37.F13 U37.F14 U37.G1 U37.G2 U37.G3 U37.G10 U37.G12 U37.G13 U37.G14 U37.H1 U37.H2 U37.H3 U37.H12 U37.H13 U37.H14 U37.J1 U37.J2 U37.J3 U37.J12 U37.J13 U37.J14 U37.K1 U37.K2 U37.K3 U37.K6 U37.K7 U37.K10 U37.K12 U37.K13 U37.K14 U37.L1 U37.L2 U37.L3 U37.L12 U37.L13 U37.L14 U37.M1 U37.M2 U37.M3 U37.M7 U37.M8 U37.M9 U37.M10 U37.M11 U37.M12 U37.M13 U37.M14 U37.N1 U37.N3 U37.N6 U37.N7 U37.N8 U37.N9 U37.N10 U37.N11 U37.N12 U37.N13 U37.N14 U37.P1 U37.P2 U37.P7 U37.P8 U37.P9 U37.P10 U37.P11 U37.P12 U37.P13 U37.P14
copper on no net: | length 1380.7
  Top Layer w0.09: 39.873,56.227 53.275,42.825 56.875,42.825 ; 39.977,56.477 53.378,43.075 57.123,43.075 57.373,42.825 57.375,42.825 ; 40.175,57 53.85,43.325 56.375,43.325 ; 40.279,57.25 53.954,43.575 56.604,43.575 56.854,43.325 56.875,43.325 ; 40.575,57.875 54.625,43.825 56.375,43.825 ; 40.679,58.125 54.729,44.075 56.625,44.075 56.875,43.825 ; 40.8,58.825 55.301,44.324 57.374,44.324 ; 40.904,59.075 55.398,44.581 57.619,44.581 57.875,44.325 ; 40.925,59.8 55.9,44.825 56.875,44.825 ; 41.028,60.049 56.002,45.075 57.104,45.075 57.354,44.825 57.375,44.825 ; 41.372,60.697 53.744,48.325 56.941,48.325 57.105,48.161 57.105,47.949 57.125,47.929 57.125,47.575 57.373,47.327 57.375,47.327 ; 41.476,60.947 53.848,48.575 57.045,48.575 57.355,48.265 57.355,48.052 57.375,48.032 57.375,47.825 ; 41.622,61.627 54.147,49.101 57.05,49.101 57.625,48.526 57.625,46.575 57.875,46.325 ; 41.725,61.877 54.251,49.351 57.153,49.351 57.815,48.69 57.815,47.025 57.859,46.879 57.875,46.825 ; 41.962,62.567 54.586,49.943 57.188,49.943 58.005,49.126 58.005,47.232 58.375,46.862 58.375,46.825 ; 42.065,62.817 54.689,50.193 57.291,50.193 58.225,49.259 58.225,47.478 58.375,47.328 58.375,47.325 ; 47.601,58.348 55.092,50.857 57.854,50.857 58.65,50.061 58.65,48.127 58.625,48.102 58.625,47.721 58.86,47.486 58.86,47.34 58.875,47.325 ; 48.037,59.122 55.493,51.666 58.113,51.666 59.091,50.688 59.091,47.963 59.125,47.929 59.125,47.575 59.375,47.325 ; 48.141,59.372 55.597,51.916 58.216,51.916 59.341,50.792 59.341,48.066 59.375,48.032 59.375,47.825 ; 48.241,58.062 55.196,51.107 57.958,51.107 58.9,50.165 58.9,48.024 58.875,47.999 58.875,47.825 ; 51.21,57.126 53.846,54.489 55.788,52.548 58.415,52.548 59.531,51.432 59.531,48.2 59.695,48.036 59.695,47.752 59.625,47.682 59.625,47.174 59.625,47.073 59.377,46.825 59.375,46.825 ; 51.386,57.303 54.023,54.666 55.891,52.798 58.519,52.798 59.781,51.536 59.781,48.304 59.945,48.14 59.945,47.649 59.875,47.579 59.875,47.07 59.875,46.825 ; 53.528,34.458 53.958,34.888 54.709,34.888 55.078,35.258 55.53,35.258 55.847,35.575 56.979,35.575 57.125,35.721 57.125,35.736 57.188,35.798 57.348,35.798 57.375,35.825 ; 55.62,35.07 55.875,35.325 56.375,35.325 ; 55.625,36.655 56.67,36.655 56.84,36.825 56.875,36.825 ; 55.625,36.869 56.566,36.869 56.771,37.075 56.979,37.075 57.125,37.221 57.125,37.575 57.375,37.825 ; 55.625,37.075 56.479,37.075 56.702,37.298 56.848,37.298 56.875,37.325 ; 55.625,39.294 55.905,39.294 56.123,39.075 56.479,39.075 56.715,39.311 56.861,39.311 56.875,39.325 ; 55.625,39.494 55.959,39.494 56.128,39.325 56.375,39.325 ; v2@55.625,40.075 56.625,40.075 56.875,39.825 ; 55.625,40.42 55.648,40.42 55.793,40.275 56.68,40.275 56.73,40.325 57.375,40.325 ; 55.625,41.075 55.897,41.075 56.087,40.885 56.543,40.885 56.733,41.075 57.125,41.075 57.375,41.325 ; 55.625,41.494 56.038,41.494 56.182,41.35 56.35,41.35 56.375,41.325 ; 55.625,41.694 56.153,41.694 56.271,41.575 56.625,41.575 56.875,41.825 ; 55.625,41.894 56.207,41.894 56.251,41.85 56.35,41.85 56.375,41.825 ; 55.625,42.094 57.123,42.094 57.141,42.075 57.491,42.075 57.721,42.305 57.855,42.305 57.875,42.325 ; 55.625,42.294 57.252,42.294 57.257,42.298 57.348,42.298 57.375,42.325 ; 55.625,42.494 57.063,42.494 57.144,42.575 58.125,42.575 58.375,42.825 ; 55.92,36.07 55.925,36.075 56.625,36.075 56.875,35.825 ; 56.082,53.397 58.764,53.397 60.225,51.936 60.225,49.675 59.995,49.445 59.995,48.575 59.995,48.344 60.068,48.271 60.125,48.214 60.125,47.429 60.125,47.075 60.375,46.825 ; 56.114,38.255 57.267,38.255 57.337,38.325 57.375,38.325 ; 56.166,40.7 56.747,40.7 56.872,40.825 56.875,40.825 ; 56.183,38.89 56.188,38.895 56.553,38.895 56.733,39.075 57.125,39.075 57.374,39.324 ; 56.185,53.647 58.868,53.647 60.475,52.04 60.475,49.571 60.245,49.341 60.245,48.575 60.245,48.448 60.375,48.318 60.375,47.325 ; 56.195,41.075 56.479,41.075 56.702,41.298 56.848,41.298 56.875,41.325 ; 56.264,39.575 56.271,39.575 57.125,39.575 57.375,39.825 ; 56.279,54.255 59.174,54.255 60.9,52.529 60.9,49.45 60.53,49.08 60.53,48.575 60.53,48.529 60.625,48.434 60.625,47.575 60.875,47.325 ; 56.382,54.505 59.278,54.505 61.15,52.633 61.15,49.346 60.78,48.976 60.78,48.632 60.875,48.537 60.875,47.825 ; 56.655,40.505 57.055,40.505 57.375,40.825 ; 57.125,34.075 57.125,35.429 57.271,35.575 57.479,35.575 57.625,35.721 57.625,36.075 57.875,36.325 ; 57.325,34.075 57.325,34.605 57.375,34.655 57.375,35.325 ; 57.525,34.075 57.525,34.441 57.585,34.501 57.585,35.152 57.625,35.192 57.625,35.467 57.848,35.69 57.848,35.798 57.875,35.825 ; 57.76,34.344 57.765,34.349 57.765,35.078 57.805,35.118 57.805,35.363 58.24,35.798 58.348,35.798 58.375,35.825 ; v2@57.775,39.875 57.775,40.187 57.875,40.287 57.875,40.325 ; v2(57.79,38.85) 57.79,39.202 57.875,39.287 57.875,39.325 ; v2@57.9,41.825 58.375,41.825 ; 57.925,34.075 57.925,34.16 57.945,34.18 57.945,35.003 57.985,35.043 57.985,35.289 58.271,35.575 58.525,35.575 58.625,35.675 58.625,36.075 58.875,36.325 ; v2(58.349,38.315) 58.375,38.341 58.375,38.825 ; v2(58.375,37.35) 58.375,37.825 ; 58.375,43.825 58.388,43.813 58.862,43.813 v2@58.875,43.8 ; v2@58.391,42.3 58.416,42.325 58.875,42.325 ; v2@58.858,40.933 58.877,40.952 58.877,41.323 58.875,41.325 ; 58.875,35.825 59.125,35.575 59.125,35.104 ; 58.875,38.325 58.928,37.865 v2(58.939,37.77) ; v2@58.875,42.8 58.875,43.325 ; v2(59.45,46.325) 59.875,46.325 ; 59.625,35.629 59.625,36.075 59.875,36.325 ; 59.925,34.442 59.925,35.225 60.125,35.425 60.125,36.125 60.375,36.375 60.375,36.825 ; 60.125,34.59 60.125,35.075 60.375,35.325 ; 60.473,34.569 60.625,34.721 60.625,36.075 60.875,36.325 ; 60.679,34.372 60.875,34.568 60.875,34.825 ; 60.875,35.325 61.125,35.075 61.125,34.485 ; 61.375,34.075 61.375,35.325 ; 61.375,35.825 61.625,35.575 61.625,35.221 61.605,35.201 61.605,34.075 ; 61.375,46.825 61.765,47.215 61.765,47.607 61.826,47.668 61.826,48.429 61.972,48.575 ; 61.375,47.325 61.585,47.535 61.585,47.681 61.625,47.721 61.625,48.504 61.85,48.729 61.85,48.875 ; 61.88,46.83 61.895,46.845 61.895,47.09 61.945,47.14 61.945,47.532 62.065,47.652 62.065,48.407 62.233,48.575 ; 62.1,34.075 62.1,35.05 62.375,35.325 ; 62.362,34.075 62.362,34.812 62.375,34.825 ; 62.375,35.825 62.625,35.575 62.625,34.075 ; 62.375,46.825 62.125,47.075 62.125,47.458 62.265,47.598 62.265,48.345 62.45,48.53 62.45,48.575 ; 62.375,47.325 62.4,47.35 62.4,47.478 62.445,47.523 62.445,48.271 62.65,48.476 62.65,48.575 ; 62.85,48.575 62.85,48.421 62.625,48.196 62.625,47.075 62.875,46.825 ; 62.875,35.325 62.898,35.302 62.898,35.156 63.125,34.929 63.125,34.164 63.085,34.124 63.085,34.075 ; 62.875,35.825 63.125,35.575 63.125,35.221 63.305,35.041 63.305,34.075 ; 62.875,36.325 63.146,36.325 63.162,36.309 63.316,36.309 v2@63.375,36.25 ; v2@62.875,37.725 62.959,37.725 63.059,37.825 63.375,37.825 ; 62.875,47.325 63.125,47.575 63.125,48.17 63.251,48.297 63.251,48.575 ; 62.875,47.825 62.875,48.175 63.05,48.35 63.05,48.575 ; 63.375,35.318 63.375,35.293 63.515,35.153 63.515,34.075 ; 63.375,35.825 63.695,35.505 63.695,34.164 63.725,34.134 63.725,34.075 ; 63.375,46.825 63.825,47.275 ; 63.375,47.325 63.65,47.6 63.65,48.575 ; 63.875,35.825 63.875,35.334 63.945,35.264 63.945,34.647 63.949,34.643 63.949,34.075 ; 63.875,46.825 63.875,46.85 64.05,47.025 64.05,48.575 ; 64.154,34.075 64.154,34.693 64.125,34.721 64.125,35.075 64.375,35.325 ; 64.375,34.075 64.375,34.825 ; 64.375,35.825 64.625,35.575 64.625,34.635 ; 64.375,46.825 64.625,47.075 64.625,47.838 64.451,48.012 64.451,48.575 ; 64.851,48.575 64.851,48.203 65.125,47.929 65.125,47.075 64.875,46.825 ; 64.875,35.325 64.889,35.311 64.889,35.165 65.125,34.929 65.125,34.486 65.075,34.436 65.075,34.075 ; 64.875,35.825 65.125,35.575 65.125,35.183 65.305,35.003 65.305,34.411 65.29,34.396 65.29,34.085 65.28,34.075 65.275,34.07 65.275,34.04 ; 65.051,48.575 65.051,48.257 65.305,48.003 65.305,47.933 65.375,47.863 65.375,47.825 ; 65.375,35.325 65.375,35.29 65.485,35.18 65.485,34.08 65.48,34.075 ; 65.375,35.825 65.675,35.525 65.675,34.075 65.675,33.925 ; 65.375,46.825 65.625,47.075 65.625,47.229 65.695,47.299 65.695,47.537 65.805,47.647 65.805,48.166 65.63,48.342 65.63,48.575 ; 65.375,47.325 65.515,47.465 65.515,47.611 65.625,47.721 65.625,48.015 65.375,48.265 ; 65.875,34.075 65.875,35.825 ; 65.875,46.825 65.875,47.462 65.985,47.572 65.985,48.267 65.875,48.377 65.875,48.575 ; 66.115,47.085 66.115,47.434 66.175,47.494 66.175,48.356 66.125,48.406 66.125,48.575 66.125,48.615 ; 66.625,34.714 66.625,34.936 ; v2@67.961,36.833 68.206,36.589 68.206,36.517 68.377,36.347 68.377,36.333 ; 68.375,36.825 ccw(c68.39,36.914) 68.379,36.824 68.444,36.816 v2(68.85,36.41) ; 68.375,46.325 68.413,46.325 68.48,46.392 68.579,46.392 68.724,46.537 68.94,46.537 69.125,46.721 69.125,46.825 69.125,46.929 69.271,47.075 69.511,47.075 69.809,47.373 69.841,47.373 ; 68.875,46.825 68.875,46.995 69.125,47.245 69.125,47.429 69.271,47.575 69.487,47.575 69.805,47.893 69.905,47.893 70.207,48.194 70.207,48.549 ; 68.889,47.339 68.889,47.485 69.125,47.721 69.125,48.118 69.582,48.575 ; 69.375,46.825 69.673,46.825 70.78,47.932 ; 69.375,47.325 69.398,47.348 69.529,47.348 69.884,47.703 70.012,47.703 70.51,48.2
  Top Layer w0.091: 65.475,33.994 65.475,34.001 65.48,34.006 65.48,34.075
  Top Layer w0.097: 63.65,48.575 63.65,48.681
  Top Layer w0.1: v2(43.9,37.12) 44.218,37.438 44.218,39.273 47.239,42.294 55.625,42.294 ; v2(44.4,37.12) 44.447,37.167 44.447,39.026 47.514,42.094 55.625,42.094 ; v2(44.8,38.125) 44.8,38.939 47.434,41.573 50.112,41.573 50.866,40.82 53.566,40.82 54.04,41.294 55.977,41.294 56.195,41.075 ; v2(45.3,38.125) 45.3,38.979 47.694,41.373 50.03,41.373 50.8,40.603 53.632,40.603 54.104,41.075 55.625,41.075 ; v2(45.8,38.125) 45.8,39.096 47.877,41.173 49.947,41.173 50.718,40.403 53.715,40.403 54.187,40.875 55.782,40.875 55.957,40.7 56.166,40.7 ; v2(45.825,36.825) 45.825,37.441 46.187,37.803 46.187,39.02 48.141,40.973 49.864,40.973 50.635,40.203 53.798,40.203 54.215,40.62 55.746,40.62 55.861,40.505 56.655,40.505 ; v2(46.325,36.825) 46.382,36.882 46.382,37.348 46.591,37.557 46.591,38.953 48.411,40.773 49.781,40.773 50.561,39.994 53.329,39.994 53.629,39.694 56.021,39.694 56.139,39.575 56.264,39.575 ; v2@46.875,36.833 46.875,38.78 48.669,40.573 49.698,40.573 50.478,39.794 53.247,39.794 53.546,39.494 55.625,39.494 ; v1(48.806,33.855) 50.209,35.258 53.188,35.258 53.573,35.643 54.396,35.643 54.727,35.974 54.727,36.37 55.012,36.655 55.625,36.655 ; v2(49.325,35.825) 49.692,35.458 53.105,35.458 53.501,35.854 54.306,35.854 54.527,36.074 54.527,36.453 54.943,36.869 55.625,36.869 ; v2(49.358,39.866) 49.83,39.394 50.019,39.394 50.021,39.392 50.476,39.392 50.478,39.394 53.081,39.394 53.381,39.094 55.843,39.094 56.047,38.89 56.183,38.89 ; v2(49.475,38.554) 49.913,38.992 50.642,38.992 50.644,38.994 52.847,38.994 53.391,38.45 54.448,38.45 54.704,38.194 55.16,38.194 55.402,38.435 55.695,38.435 55.875,38.255 56.114,38.255 ; v2(49.889,39.866) 50.162,39.594 53.164,39.594 53.464,39.294 55.625,39.294 ; v1(50.389,33.869) 50.482,33.869 51.471,34.858 53.36,34.858 53.765,35.263 54.553,35.263 54.939,35.648 55.355,35.648 55.777,36.07 55.92,36.07 ; v1(51.631,33.875) 52.214,34.458 53.528,34.458 ; v2(52.031,42.8) 52.337,42.494 55.625,42.494 ; v2(52.175,41.475) 52.525,41.125 52.849,41.125 53.417,41.694 55.625,41.694 ; v2(52.675,41.475) 53.094,41.894 55.625,41.894 ; 52.871,34.268 53.617,34.268 54.052,34.703 54.372,34.703 54.785,34.703 55.152,35.07 55.62,35.07 ; v2(53.389,41.17) 53.712,41.494 55.625,41.494 ; v2(53.45,36.225) 53.9,36.675 54.139,36.675 54.789,37.325 56.375,37.325 ; 54.014,29.76 55.661,29.76 56.837,30.936 56.837,31.895 57.325,32.383 57.325,34.075 ; v2(54.175,36.225) 54.175,36.384 54.866,37.075 55.625,37.075 ; v2(54.436,40.077) 54.779,40.42 55.625,40.42 ; v2(55.458,40.07) 55.463,40.075 v2@55.625,40.075 ; v2(56.956,32.51) 56.956,32.865 57.125,33.033 57.125,34.075 ; v2(57.271,30.195) 57.925,30.848 57.925,34.075 ; v2(57.271,30.982) 57.725,31.436 57.725,34.309 57.76,34.344 ; v2(57.275,31.8) 57.525,32.05 57.525,34.075 ; 57.375,43.825 57.77,43.825 v2(57.782,43.813) ; v2(57.79,40.85) 57.816,40.825 58.375,40.825 ; 57.875,41.325 57.899,41.325 57.999,41.425 v2@58.35,41.425 ; 57.875,43.325 v2(58.348,43.3) ; 58.325,30.282 58.325,33.533 58.325,34.354 58.375,34.404 58.375,34.825 ; v2(58.325,39.355) 58.375,39.405 58.375,39.825 ; v2(58.396,46.369) 58.875,46.325 ; v2(58.875,41.75) 58.932,41.807 59.039,41.807 59.056,41.825 59.375,41.825 ; 58.875,45.325 v2(58.875,45.9) ; 59.125,35.104 59.454,34.775 59.454,34.234 59.623,34.064 59.623,31.68 59.778,31.525 59.778,31.178 v2(59.781,31.175) ; v2@59.272,42.372 59.272,42.453 59.375,42.556 59.375,42.825 ; v2@59.3,39.367 59.316,39.465 59.375,39.825 ; v2(59.469,37.256) 59.802,37.313 59.875,37.325 ; 59.625,35.629 59.729,35.525 59.729,34.27 59.823,34.176 59.823,32.01 60.395,31.439 60.395,30.77 v2(60.375,30.75) ; 59.925,34.442 60.023,34.344 60.023,32.093 60.451,31.666 60.469,31.666 v2(60.96,31.175) ; 60.125,34.59 60.223,34.492 60.223,32.412 60.408,32.228 v2(60.408,32.204) ; v2@60.375,45.325 60.875,45.325 ; 60.473,34.569 60.423,34.52 60.423,32.746 v2(60.96,32.21) ; 60.679,34.372 60.623,34.316 60.623,33.097 v2(60.956,32.765) ; v2(60.973,33.601) 60.973,34.333 61.125,34.485 ; 61.225,54.759 62.25,53.734 62.25,48.594 62.233,48.577 62.233,48.575 ; 61.301,54.4 62.05,53.651 62.05,48.677 62.045,48.672 62.045,48.648 61.972,48.575 ; 61.325,53.425 61.637,53.113 61.637,48.792 61.375,48.53 61.375,47.825 ; v2(61.375,46.325) 61.875,46.325 ; 61.389,53.962 61.85,53.501 61.85,48.875 ; 61.65,54.617 62.45,53.817 62.45,48.575 ; 62.075,54.475 62.65,53.9 62.65,48.575 ; 62.375,44.825 v2(62.375,45.3) ; 62.649,54.184 62.85,53.983 62.85,48.575 ; 63.05,48.575 63.05,54.753 ; 63.25,55.155 63.25,48.576 63.251,48.575 ; 63.375,36.825 63.381,36.831 63.819,36.831 v2@63.875,36.775 ; v2@63.375,37.275 63.425,37.325 63.875,37.325 ; 63.375,47.825 63.375,48.159 63.451,48.235 63.451,48.575 63.451,48.597 63.45,48.598 63.45,55.572 ; 63.65,48.681 63.65,55.856 ; 63.825,47.275 63.85,47.3 63.85,48.575 63.85,56.423 ; 63.875,36.325 64.219,36.271 64.354,36.271 v2@64.375,36.25 ; v2(63.9,37.925) 63.94,37.885 64.055,37.885 64.375,37.825 ; 63.949,34.075 63.949,30.385 63.945,30.382 63.945,29.105 64.017,29.033 64.017,28.387 ; 64.05,48.575 64.05,56.294 ; 64.251,55.893 64.251,47.763 64.375,47.638 64.375,47.325 ; 64.375,34.075 64.375,29.626 64.904,29.097 64.904,28.387 ; 64.375,36.825 64.379,36.829 64.379,37.346 v2(64.375,37.35) ; 64.451,48.575 64.451,55.733 ; 64.625,34.635 64.625,29.701 65.331,28.995 65.331,28.141 65.5,27.973 65.5,26.55 ; 64.651,55.281 64.651,48.074 64.875,47.85 64.875,47.825 ; v2(64.8,37.75) 64.875,37.325 ; 64.851,48.575 64.851,54.9 65.325,55.374 ; 64.875,34.825 64.875,32.955 64.849,32.929 64.849,29.81 65.531,29.128 65.531,28.224 65.956,27.799 65.956,26.206 65.462,25.712 65.01,25.712 ; 64.875,36.325 v2(64.875,36.829) ; 65.051,48.575 65.051,54.817 65.525,55.291 ; 65.075,34.075 65.075,32.872 65.049,32.846 65.049,29.893 v2(65.956,28.986) ; 65.275,34.04 65.275,32.41 65.249,32.384 65.249,30.526 v2(65.5,30.275) ; v2@65.375,36.275 65.375,36.825 ; 65.375,37.825 65.55,37.65 65.55,37.174 65.74,36.985 65.74,36.76 v2@65.775,36.725 ; 65.475,33.994 65.475,32.327 65.449,32.301 65.449,30.993 66.003,30.439 v2(66.003,29.72) ; 65.675,33.925 65.675,32.244 65.649,32.218 65.649,31.294 v2(65.999,30.944) ; 65.875,34.075 65.875,32.555 65.999,32.431 65.999,32.073 ; 66.375,34.825 66.375,32.814 66.854,32.335 ; 66.375,35.325 66.12,35.07 66.12,34.719 66.155,34.684 66.155,33.97 66.155,32.723 66.634,32.244 ; 66.625,34.714 66.625,33.208 67.52,32.313 67.52,30.227 68.321,29.425 70.516,29.425 ; 66.625,34.936 66.625,35.075 66.875,35.325 ; 66.875,34.825 66.875,34.075 66.875,33.269 67.74,32.404 67.74,30.318 68.412,29.645 70.607,29.645
  Top Layer w0.11: 56.657,28.898 56.73,28.825 60.735,28.825 62.1,30.19 62.1,34.075 ; 56.938,29.15 60.654,29.15 61.85,30.346 61.85,34.075 61.85,35.15 61.875,35.175 ; 58.066,29.495 60.595,29.495 61.605,30.505 61.605,34.075 ; v2(60.389,30.112) 60.422,30.112 61.375,31.065 61.375,34.075 ; 60.776,28.495 62.362,30.081 62.362,34.075 ; 61.545,28.065 61.545,28.845 62.625,29.925 62.625,34.075 ; 61.56,26.465 62.145,26.465 62.957,27.277 62.957,28.826 63.085,28.954 63.085,34.075 ; 61.56,27.24 62.115,27.24 62.747,27.872 62.747,28.913 62.875,29.041 62.875,34.075 62.875,34.825 ; 61.875,35.178 61.875,35.793 ; v2@62.375,36.25 62.375,36.825 ; v2@62.375,37.275 62.375,37.825 ; v2@62.875,36.75 62.875,37.325 ; 63.167,26.426 63.167,28.739 63.305,28.877 63.305,34.075 ; 63.377,25.821 63.377,28.652 63.515,28.79 63.515,34.075 ; 63.587,28.565 63.725,28.703 63.725,34.075 ; 63.797,27.389 64.457,28.048 64.457,29.066 64.154,29.369 64.154,34.075 ; 65.375,48.265 65.375,54.493 67.076,56.194 68.179,57.298 68.8,57.918 ; 65.63,48.575 65.63,54.198 69.225,57.793 ; 65.875,48.575 65.875,53.79 69.841,57.756 ; 66.115,47.085 66.375,46.825 ; 66.125,48.615 66.125,53.21 67.275,54.36 67.275,54.59 68.803,56.118 69.018,56.118 70.375,57.475 70.375,58.349 ; 66.375,47.325 66.375,52.65 67.75,54.025 67.75,54.538 68.909,55.697 69.051,55.697 70.976,57.622 70.976,58.076 ; v2(66.45,46.425) 66.475,46.425 66.875,46.825 ; 68.875,47.825 68.884,47.834 68.884,48.387 69.706,49.209 69.909,49.209 74.284,53.584 ; 69.582,48.575 69.831,48.824 70.025,48.824 74.476,53.275 ; 70.207,48.549 74.617,52.959 ; 70.78,47.932 75.008,52.16
  Top Layer w0.15: v2(59.989,37.734) v2(59.989,37.734) 60.264,37.736 60.353,37.825 60.375,37.825 ; v2(60.95,37.8) 60.971,37.779 61.307,37.779 61.353,37.825 61.375,37.825
  Top Layer w0.25: v1(68.584,30.569) 68.584,31.233
  Bottom Layer w0.09: 57.296,40 57.517,40 57.582,39.934 57.731,39.934 v2(57.79,39.875)
  Bottom Layer w0.1: v2(49.475,38.554) v2@49.475,38.632 ; v2@52.028,42.803 v2(52.031,42.8) ; 56.233,43.813 v2(57.782,43.813) ; 56.314,43.463 57.927,43.463 58.264,43.8 v2(58.85,43.8) ; 56.899,40.849 57.286,40.849 57.287,40.85 v2(57.79,40.85) ; 57.509,43.191 57.742,43.191 57.821,43.27 58.003,43.27 58.033,43.3 v2(58.348,43.3) ; 57.635,42.575 57.64,42.57 58.111,42.57 58.241,42.7 58.25,42.7 58.29,42.74 v2(58.875,42.74) ; 57.642,42.18 57.923,42.18 58.177,41.926 58.553,41.926 58.999,42.371 59.286,42.371 v2(59.29,42.375) ; 57.792,42.385 57.794,42.384 57.991,42.384 58.183,42.384 58.209,42.357 58.334,42.357 v2@58.391,42.3 ; 58.287,40.933 v2@58.858,40.933 ; 59.375,46.875 59.089,46.589 59.089,46.192 59.431,45.85 59.478,45.85 60.003,45.325 v2@60.375,45.325 ; v2(59.45,46.325) 59.441,46.334 59.441,46.616 59.55,46.725 59.575,46.75 ; v2(61.375,46.325) 61.375,48.53 66.362,53.518 ; 62.787,24.149 62.787,33.049 63.813,34.075 64.058,34.32 64.058,35.64 63.714,35.984 63.714,36.413 63.529,36.598 63.529,36.999 64.28,37.75 v2(64.8,37.75) ; 62.987,24.066 62.987,32.683 62.987,32.966 64.096,34.075 64.248,34.227 64.248,35.719 63.973,35.994 63.973,36.342 64.375,36.744 v2(64.375,37.35) ; 63.187,23.983 63.187,32.883 64.379,34.075 64.438,34.135 64.438,35.85 64.438,35.858 64.338,35.959 64.338,36.213 v2@64.375,36.25 ; 63.387,23.901 63.387,32.8 64.579,33.992 64.579,33.995 64.579,35.808 64.798,36.026 64.798,36.474 64.866,36.543 64.866,36.82 v2(64.875,36.829) ; 63.587,23.818 63.587,32.717 64.858,33.989 64.858,34.075 64.858,35.78 64.988,35.909 64.988,36.395 65.38,36.787 65.414,36.821 65.608,36.821 65.704,36.725 v2@65.775,36.725
  Bottom Layer w0.11: 57.752,31.425 60.402,34.075 60.865,34.538 60.865,35.768 v2@61.335,36.239 ; 57.777,30.55 60.458,33.23 60.458,33.588 61.525,34.655 61.525,35.349 62.375,36.199 v2(62.375,36.24) ; 57.977,32.227 60.475,34.725 60.475,35.978 61.249,36.751 v2@61.872,36.751 ; 58.127,33.021 59.18,34.075 59.653,34.548 59.653,36.273 60.654,37.274 61.955,37.274 v2@62.374,37.274 ; 61.525,31.919 61.525,33.498 62.528,34.501 62.528,35.901 62.875,36.248 v2@62.875,36.75 ; 61.981,31.469 61.981,33.039 63.375,34.433 v2@63.375,36.25 ; v2(62.375,45.3) 62.375,45.848 62.045,46.178 61.906,46.317 61.906,48.34 67.341,53.775
  Bottom Layer w0.2: 69.826,34.72 69.88,34.72 ; 70.043,34.557 70.126,34.557
  other v2: 61.3,36.24 63.375,36.24 64.375,36.24 65.375,36.24 61.875,36.74 62.875,36.74 65.78,36.73 63.9,36.775 46.875,36.825 67.96,36.825 62.375,37.24 63.385,37.265 62.875,37.76 59.345,39.355 58.858,40.91 58.28,41.421 57.79,41.825 58.4,42.275 60.375,45.35

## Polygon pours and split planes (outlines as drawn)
GND on Signal Layer 2 "GND_L03_P054" (solid, remove dead copper, pour order 54): 0,79.6 120,79.6 120,0 0,0
1V8 on Signal Layer 2 "1V8_L03_P052" (solid, pour order 52): 29.175,64.6 29.175,61.472 70.193,61.472 70.252,51.21 82.713,51.21 82.713,64.6
VDD2_DDR on Signal Layer 2 "VDD_DDR" (solid, remove dead copper, pour order 48): 65.275,36.84 66.119,36.84 66.119,36.815 67.3,35.634 67.3,35.25 69.303,33.247 90.16,33.247 90.16,49.111 73.749,49.176 64.94,57.985 19.353,57.985 14.746,53.378 14.746,46.14 15.418,45.468 16.716,45.468 17.719,46.471 17.719,51.775 18.039,52.095 62.26,52.095 63.82,50.536 66.079,48.276 66.079,46.314 66.079,45.291 65.395,44.606 65.395,42.844 65.275,42.724
VDDCORE on Signal Layer 2 "VDDCORE" (solid, remove dead copper, pour order 46): 61.618,43.605 61.618,45.055 59.673,47 42.245,47 42.245,41.019 62.343,41.019 62.343,42.83
VDDCPU on Signal Layer 2 "VDDCPU" (solid, remove dead copper, pour order 47): 65.318,42.75 63.344,40.776 63.333,40.775 61.131,40.775 61.131,44.645 61.131,45.532 60.118,46.545 34.955,46.545 34.955,48.62 35.005,48.67 34.675,49 28.643,49 28.555,48.912 27.616,49.85 17.819,49.85 17.719,49.75 17.719,51.775 19.343,53.4 28.217,53.4 29.103,52.513 29.103,52.5 61.855,52.5 66.016,48.339 66.016,44.697 65.318,43.998
VDDGPU on Signal Layer 2 "VDDGPU" (solid, remove dead copper, pour order 45): 65.482,41.332 65.482,37.836 67.041,36.277 67.041,32.841 64.416,30.216 41.23,30.216 37.77,33.607 37.77,38.917 35.099,41.523 35.099,43.759 36.63,45.29 42.13,45.29 42.13,40.863 41.049,39.782 41.049,37.54 42.874,35.715 57.874,35.715 60.107,37.923 61.767,37.923 61.941,38.097 61.941,38.49 61.941,41.332
VDDIO on Signal Layer 2 "VDDIO" (solid, remove dead copper, pour order 49): 62.352,38.39 61.735,37.772 60.085,37.772 57.878,35.564 42.878,35.564 41.053,37.389 41.053,39.646 42.445,41.038 61.524,41.038 62.352,40.21
3V3 on Signal Layer 2 "3V3_L4" (solid, remove dead copper, pour order 50): 26.5,29.394 26.439,29.394 6.483,29.394 4.211,29.394 4.211,35.822 4.211,52.011 12.936,52.011 12.936,41.55 13.947,40.539 26.5,40.539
